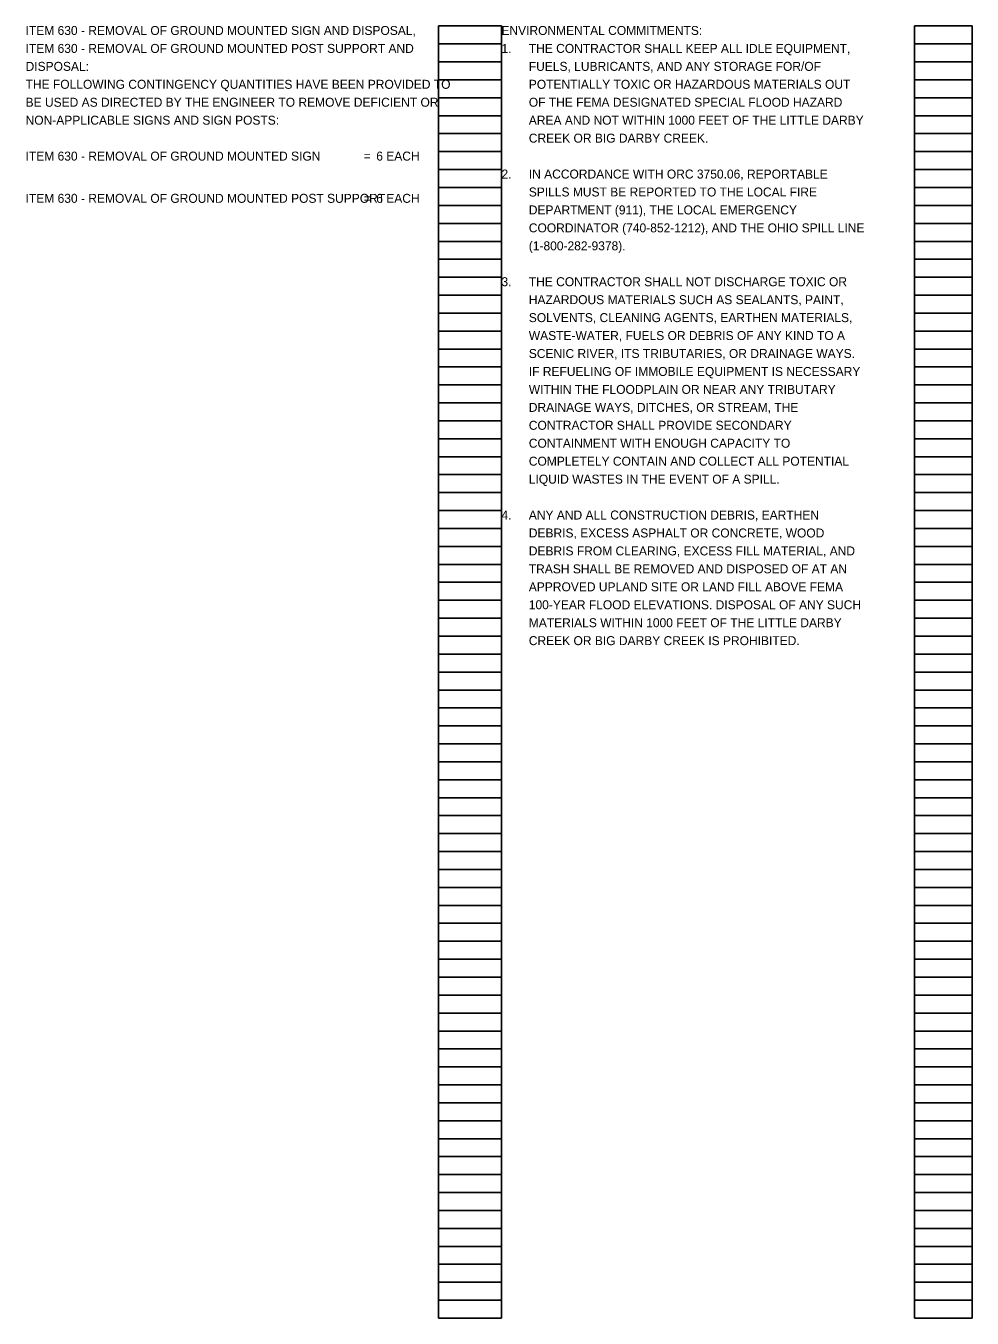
# Model space of a CAD drawing. Extents: x 0 to 32, y 0 to 21.1.
# Drawn here: x 17.24 to 32, y 0.98 to 21.14 of the extents above; entities that cross this region are included whole.
import ezdxf

# ---------------------------------------------------------------- set-up
doc = ezdxf.new("R2010")
doc.units = 0
doc.layers.add('SH_Data', color=7, linetype='Continuous')
doc.layers.add('SH_Text', color=7, linetype='Continuous')

msp = doc.modelspace()

# ---------------------------------------------------------------- linework, layer by layer
at = {"layer": 'SH_Data'}
for p, q in [((23.68, 0.98), (23.68, 21.14)), ((23.68, 21.14), (24.66, 21.14)), ((24.66, 0.98), (24.66, 21.14)), ((31.1, 0.98), (31.1, 21.14)), ((31.1, 21.14), (32, 21.14)), ((32, 0.98), (32, 21.14)), ((23.68, 20.86), (24.66, 20.86)), ((31.1, 20.86), (32, 20.86)), ((23.68, 20.58), (24.66, 20.58)), ((31.1, 20.58), (32, 20.58)), ((23.68, 20.3), (24.66, 20.3)), ((31.1, 20.3), (32, 20.3)), ((23.68, 20.02), (24.66, 20.02)), ((31.1, 20.02), (32, 20.02)), ((23.68, 19.74), (24.66, 19.74)), ((31.1, 19.74), (32, 19.74)), ((23.68, 19.46), (24.66, 19.46)), ((31.1, 19.46), (32, 19.46)), ((23.68, 19.18), (24.66, 19.18)), ((31.1, 19.18), (32, 19.18)), ((23.68, 18.9), (24.66, 18.9)), ((31.1, 18.9), (32, 18.9)), ((23.68, 18.62), (24.66, 18.62)), ((31.1, 18.62), (32, 18.62)), ((23.68, 18.34), (24.66, 18.34)), ((31.1, 18.34), (32, 18.34)), ((23.68, 18.06), (24.66, 18.06)), ((31.1, 18.06), (32, 18.06)), ((23.68, 17.78), (24.66, 17.78)), ((31.1, 17.78), (32, 17.78)), ((23.68, 17.5), (24.66, 17.5)), ((31.1, 17.5), (32, 17.5)), ((23.68, 17.22), (24.66, 17.22)), ((31.1, 17.22), (32, 17.22)), ((23.68, 16.94), (24.66, 16.94)), ((31.1, 16.94), (32, 16.94)), ((23.68, 16.66), (24.66, 16.66)), ((31.1, 16.66), (32, 16.66)), ((23.68, 16.38), (24.66, 16.38)), ((31.1, 16.38), (32, 16.38)), ((23.68, 16.1), (24.66, 16.1)), ((31.1, 16.1), (32, 16.1)), ((23.68, 15.82), (24.66, 15.82)), ((31.1, 15.82), (32, 15.82)), ((23.68, 15.54), (24.66, 15.54)), ((31.1, 15.54), (32, 15.54)), ((23.68, 15.26), (24.66, 15.26)), ((31.1, 15.26), (32, 15.26)), ((23.68, 14.98), (24.66, 14.98)), ((31.1, 14.98), (32, 14.98)), ((23.68, 14.7), (24.66, 14.7)), ((31.1, 14.7), (32, 14.7)), ((23.68, 14.42), (24.66, 14.42)), ((31.1, 14.42), (32, 14.42)), ((23.68, 14.14), (24.66, 14.14)), ((31.1, 14.14), (32, 14.14)), ((23.68, 13.86), (24.66, 13.86)), ((31.1, 13.86), (32, 13.86)), ((23.68, 13.58), (24.66, 13.58)), ((31.1, 13.58), (32, 13.58)), ((23.68, 13.3), (24.66, 13.3)), ((31.1, 13.3), (32, 13.3)), ((23.68, 13.02), (24.66, 13.02)), ((31.1, 13.02), (32, 13.02)), ((23.68, 12.74), (24.66, 12.74)), ((31.1, 12.74), (32, 12.74)), ((23.68, 12.46), (24.66, 12.46)), ((31.1, 12.46), (32, 12.46)), ((23.68, 12.18), (24.66, 12.18)), ((31.1, 12.18), (32, 12.18)), ((23.68, 11.9), (24.66, 11.9)), ((31.1, 11.9), (32, 11.9)), ((23.68, 11.62), (24.66, 11.62)), ((31.1, 11.62), (32, 11.62)), ((23.68, 11.34), (24.66, 11.34)), ((31.1, 11.34), (32, 11.34)), ((23.68, 11.06), (24.66, 11.06)), ((31.1, 11.06), (32, 11.06)), ((23.68, 10.78), (24.66, 10.78)), ((31.1, 10.78), (32, 10.78)), ((23.68, 10.5), (24.66, 10.5)), ((31.1, 10.5), (32, 10.5)), ((23.68, 10.22), (24.66, 10.22)), ((31.1, 10.22), (32, 10.22)), ((23.68, 9.94), (24.66, 9.94)), ((31.1, 9.94), (32, 9.94)), ((23.68, 9.66), (24.66, 9.66)), ((31.1, 9.66), (32, 9.66)), ((23.68, 9.38), (24.66, 9.38)), ((31.1, 9.38), (32, 9.38)), ((23.68, 9.1), (24.66, 9.1)), ((31.1, 9.1), (32, 9.1)), ((23.68, 8.82), (24.66, 8.82)), ((31.1, 8.82), (32, 8.82)), ((23.68, 8.54), (24.66, 8.54)), ((31.1, 8.54), (32, 8.54)), ((23.68, 8.26), (24.66, 8.26)), ((31.1, 8.26), (32, 8.26)), ((23.68, 7.98), (24.66, 7.98)), ((31.1, 7.98), (32, 7.98)), ((23.68, 7.7), (24.66, 7.7)), ((31.1, 7.7), (32, 7.7)), ((23.68, 7.42), (24.66, 7.42)), ((31.1, 7.42), (32, 7.42)), ((23.68, 7.14), (24.66, 7.14)), ((31.1, 7.14), (32, 7.14)), ((23.68, 6.86), (24.66, 6.86)), ((31.1, 6.86), (32, 6.86)), ((23.68, 6.58), (24.66, 6.58)), ((31.1, 6.58), (32, 6.58)), ((23.68, 6.3), (24.66, 6.3)), ((31.1, 6.3), (32, 6.3)), ((23.68, 6.02), (24.66, 6.02)), ((31.1, 6.02), (32, 6.02)), ((23.68, 5.74), (24.66, 5.74)), ((31.1, 5.74), (32, 5.74)), ((23.68, 5.46), (24.66, 5.46)), ((31.1, 5.46), (32, 5.46)), ((23.68, 5.18), (24.66, 5.18)), ((31.1, 5.18), (32, 5.18)), ((23.68, 4.9), (24.66, 4.9)), ((31.1, 4.9), (32, 4.9)), ((23.68, 4.62), (24.66, 4.62)), ((31.1, 4.62), (32, 4.62)), ((23.68, 4.34), (24.66, 4.34)), ((31.1, 4.34), (32, 4.34)), ((23.68, 4.06), (24.66, 4.06)), ((31.1, 4.06), (32, 4.06)), ((23.68, 3.78), (24.66, 3.78)), ((31.1, 3.78), (32, 3.78)), ((23.68, 3.5), (24.66, 3.5)), ((31.1, 3.5), (32, 3.5)), ((23.68, 3.22), (24.66, 3.22)), ((31.1, 3.22), (32, 3.22)), ((23.68, 2.94), (24.66, 2.94)), ((31.1, 2.94), (32, 2.94)), ((23.68, 2.66), (24.66, 2.66)), ((31.1, 2.66), (32, 2.66)), ((23.68, 2.38), (24.66, 2.38)), ((31.1, 2.38), (32, 2.38)), ((23.68, 2.1), (24.66, 2.1)), ((31.1, 2.1), (32, 2.1)), ((23.68, 1.82), (24.66, 1.82)), ((31.1, 1.82), (32, 1.82)), ((23.68, 1.54), (24.66, 1.54)), ((31.1, 1.54), (32, 1.54)), ((23.68, 1.26), (24.66, 1.26)), ((31.1, 1.26), (32, 1.26)), ((23.68, 0.98), (24.66, 0.98)), ((31.1, 0.98), (32, 0.98))]:
    msp.add_line(p, q, dxfattribs=at)

# ---------------------------------------------------------------- texts
for s, p in [('ITEM 630 - REMOVAL OF GROUND MOUNTED SIGN AND DISPOSAL,', (17.24, 21)), ('ITEM 630 - REMOVAL OF GROUND MOUNTED POST SUPPORT AND ', (17.24, 20.72)), ('DISPOSAL:', (17.24, 20.44)), ('THE FOLLOWING CONTINGENCY QUANTITIES HAVE BEEN PROVIDED TO ', (17.24, 20.16)), ('BE USED AS DIRECTED BY THE ENGINEER TO REMOVE DEFICIENT OR ', (17.24, 19.88)), ('NON-APPLICABLE SIGNS AND SIGN POSTS:', (17.24, 19.6))]:
    msp.add_text(s, height=0.14, dxfattribs=at).set_placement(p)
at = {"layer": 'SH_Text'}
for s, p in [('ENVIRONMENTAL COMMITMENTS:', (24.66, 21)), ('1.', (24.66, 20.72)), ('THE CONTRACTOR SHALL KEEP ALL IDLE EQUIPMENT, ', (25.087, 20.72)), ('FUELS, LUBRICANTS, AND ANY STORAGE FOR/OF ', (25.087, 20.44)), ('POTENTIALLY TOXIC OR HAZARDOUS MATERIALS OUT ', (25.087, 20.16)), ('OF THE FEMA DESIGNATED SPECIAL FLOOD HAZARD ', (25.087, 19.88)), ('AREA AND NOT WITHIN 1000 FEET OF THE LITTLE DARBY ', (25.087, 19.6)), ('CREEK OR BIG DARBY CREEK.', (25.087, 19.32)), ('ITEM 630 - REMOVAL OF GROUND MOUNTED SIGN', (17.24, 19.04)), ('6 EACH', (22.708, 19.04)), ('=', (22.511, 19.04)), ('2.', (24.66, 18.76)), ('IN ACCORDANCE WITH ORC 3750.06, REPORTABLE ', (25.087, 18.76)), ('SPILLS MUST BE REPORTED TO THE LOCAL FIRE ', (25.087, 18.48)), ('ITEM 630 - REMOVAL OF GROUND MOUNTED POST SUPPORT', (17.24, 18.381)), ('=', (22.511, 18.381)), ('6 EACH', (22.708, 18.381)), ('DEPARTMENT (911), THE LOCAL EMERGENCY ', (25.087, 18.2)), ('COORDINATOR (740-852-1212), AND THE OHIO SPILL LINE ', (25.087, 17.92)), ('(1-800-282-9378).', (25.087, 17.64)), ('3.', (24.66, 17.08)), ('THE CONTRACTOR SHALL NOT DISCHARGE TOXIC OR ', (25.087, 17.08)), ('HAZARDOUS MATERIALS SUCH AS SEALANTS, PAINT, ', (25.087, 16.8)), ('SOLVENTS, CLEANING AGENTS, EARTHEN MATERIALS, ', (25.087, 16.52)), ('WASTE-WATER, FUELS OR DEBRIS OF ANY KIND TO A ', (25.087, 16.24)), ('SCENIC RIVER, ITS TRIBUTARIES, OR DRAINAGE WAYS. ', (25.087, 15.96)), ('IF REFUELING OF IMMOBILE EQUIPMENT IS NECESSARY ', (25.087, 15.68)), ('WITHIN THE FLOODPLAIN OR NEAR ANY TRIBUTARY ', (25.087, 15.4)), ('DRAINAGE WAYS, DITCHES, OR STREAM, THE ', (25.087, 15.12)), ('CONTRACTOR SHALL PROVIDE SECONDARY ', (25.087, 14.84)), ('CONTAINMENT WITH ENOUGH CAPACITY TO ', (25.087, 14.56)), ('COMPLETELY CONTAIN AND COLLECT ALL POTENTIAL ', (25.087, 14.28)), ('LIQUID WASTES IN THE EVENT OF A SPILL.', (25.087, 14)), ('4.', (24.66, 13.44)), ('ANY AND ALL CONSTRUCTION DEBRIS, EARTHEN ', (25.087, 13.44)), ('DEBRIS, EXCESS ASPHALT OR CONCRETE, WOOD ', (25.087, 13.16)), ('DEBRIS FROM CLEARING, EXCESS FILL MATERIAL, AND ', (25.087, 12.88)), ('TRASH SHALL BE REMOVED AND DISPOSED OF AT AN ', (25.087, 12.6)), ('APPROVED UPLAND SITE OR LAND FILL ABOVE FEMA ', (25.087, 12.32)), ('100-YEAR FLOOD ELEVATIONS. DISPOSAL OF ANY SUCH ', (25.087, 12.04)), ('MATERIALS WITHIN 1000 FEET OF THE LITTLE DARBY ', (25.087, 11.76)), ('CREEK OR BIG DARBY CREEK IS PROHIBITED.', (25.087, 11.48))]:
    msp.add_text(s, height=0.14, dxfattribs=at).set_placement(p)

doc.saveas('drawing.dxf')
